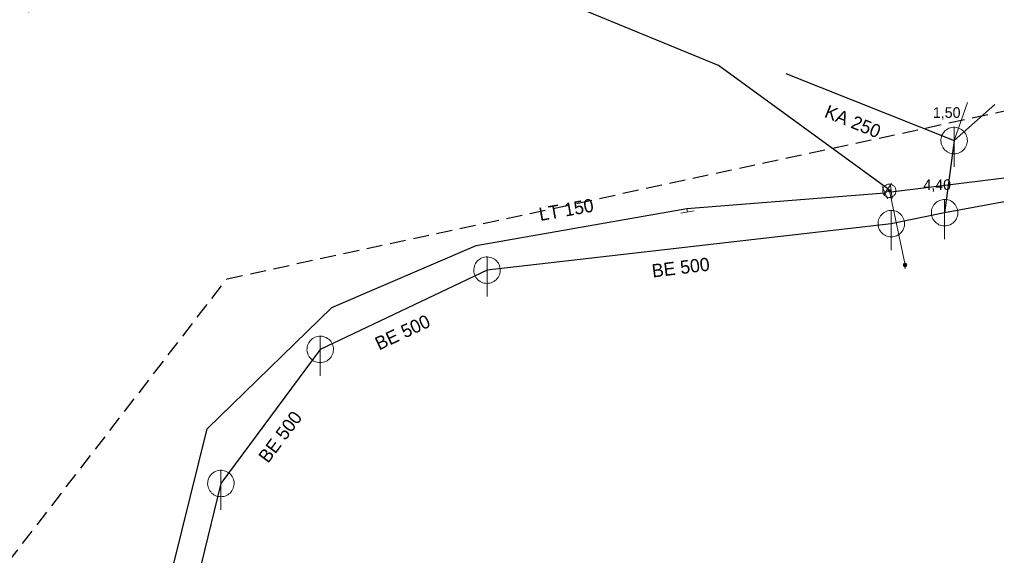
# Model space of a CAD drawing. Extents: x -687013 to -686506, y -973869 to -973672.
# Drawn here: x -686949.6 to -686875.8, y -973756 to -973715.5 of the extents above; entities that cross this region are included whole.
import ezdxf

# ---------------------------------------------------------------- set-up
doc = ezdxf.new("R2010")
doc.units = 0
doc.header["$LTSCALE"] = 0.4
doc.linetypes.add('MEDIUM_DASHED', pattern=[4.5, 3, -1.5])
doc.layers.add('1', color=7, linetype='Continuous')
for name, color, linetype, lineweight in [('11', 7, 'Continuous', 13), ('14', 7, 'Continuous', 25), ('17', 7, 'Continuous', 25), ('22', 7, 'Continuous', 13), ('34', 7, 'Continuous', 13), ('47', 7, 'Continuous', 13), ('63', 7, 'MEDIUM_DASHED', 25), ('9', 7, 'Continuous', 13)]:
    doc.layers.add(name, color=color, linetype=linetype, lineweight=lineweight)

msp = doc.modelspace()

# ---------------------------------------------------------------- linework, layer by layer
at = {"layer": '11'}
for p in [(-686877.96, -973721.82), (-686875.89, -973721.97)]:
    msp.add_line(p, (-686878.96, -973724.68), dxfattribs=at)
at = {"layer": '14'}
for p, q in [((-686891.67, -973719.62), (-686878.96, -973724.68)), ((-686849.73, -973724.67), (-686879.68, -973730.129)), ((-686883.71, -973730.96), (-686914.257, -973734.469)), ((-686914.257, -973734.469), (-686926.861, -973740.452)), ((-686926.861, -973740.452), (-686934.37, -973750.579)), ((-686934.37, -973750.579), (-686937.96, -973765.178))]:
    msp.add_line(p, q, dxfattribs=at)
at = {"layer": '14', "lineweight": 13}
for p, q in [((-686883.855, -973728.474), (-686883.979, -973728.339)), ((-686883.855, -973728.474), (-686882.671, -973734.074)), ((-686899.151, -973729.811), (-686899.109, -973730.079))]:
    msp.add_line(p, q, dxfattribs=at)
at = {"layer": '14'}
msp.add_lwpolyline([(-686878.96, -973724.68), (-686879.68, -973730.129), (-686883.71, -973730.96)], dxfattribs=at)
at = {"layer": '14', "lineweight": 13}
msp.add_lwpolyline([(-686883.709, -973728.57), (-686883.855, -973728.474), (-686884.189, -973728.62)], dxfattribs=at)
at = {"layer": '17'}
for points in [[(-686883.979, -973728.339), (-686896.774, -973719.019), (-686918.904, -973709.9), (-686935.168, -973708.778), (-686948.922, -973714.994)], [(-686778.16, -973716.008), (-686787.234, -973721.504), (-686796.6, -973724.188), (-686817.64, -973721.881), (-686819.859, -973721.829), (-686837.05, -973722.085), (-686859.074, -973725.682), (-686861.337, -973725.804), (-686883.709, -973728.57)], [(-686976.761, -973790.276), (-686962.561, -973784.848), (-686950.728, -973778.526), (-686943.195, -973771.934), (-686939.23, -973761.912), (-686935.397, -973746.442), (-686925.984, -973737.294), (-686915.07, -973732.61), (-686899.151, -973729.811), (-686884.189, -973728.62)]]:
    msp.add_lwpolyline(points, dxfattribs=at)
at = {"layer": '22'}
for p, q in [((-686878.96, -973726.68), (-686878.959, -973723.68)), ((-686879.68, -973732.13), (-686879.679, -973729.13)), ((-686883.71, -973732.96), (-686883.709, -973729.96)), ((-686914.257, -973736.469), (-686914.256, -973733.469)), ((-686926.861, -973742.452), (-686926.86, -973739.452)), ((-686934.37, -973752.579), (-686934.369, -973749.579))]:
    msp.add_line(p, q, dxfattribs=at)
for points in [[(-686877.96, -973724.68), (-686877.965, -973724.571), (-686877.983, -973724.463), (-686878.013, -973724.357), (-686878.053, -973724.256), (-686878.105, -973724.159), (-686878.167, -973724.069), (-686878.239, -973723.986), (-686878.319, -973723.912), (-686878.407, -973723.846), (-686878.501, -973723.791), (-686878.601, -973723.746), (-686878.706, -973723.713), (-686878.813, -973723.691), (-686878.922, -973723.681), (-686879.032, -973723.683), (-686879.14, -973723.697), (-686879.247, -973723.722), (-686879.35, -973723.759), (-686879.448, -973723.808), (-686879.54, -973723.866), (-686879.626, -973723.935), (-686879.703, -973724.012), (-686879.772, -973724.098), (-686879.831, -973724.19), (-686879.879, -973724.288), (-686879.916, -973724.391), (-686879.942, -973724.498), (-686879.956, -973724.606), (-686879.959, -973724.716), (-686879.949, -973724.825), (-686879.928, -973724.932), (-686879.894, -973725.036), (-686879.85, -973725.136), (-686879.795, -973725.231), (-686879.729, -973725.319), (-686879.655, -973725.399), (-686879.572, -973725.471), (-686879.482, -973725.533), (-686879.386, -973725.585), (-686879.284, -973725.626), (-686879.179, -973725.656), (-686879.071, -973725.674), (-686878.961, -973725.68), (-686878.852, -973725.674), (-686878.744, -973725.656), (-686878.639, -973725.627), (-686878.537, -973725.586), (-686878.44, -973725.534), (-686878.35, -973725.472), (-686878.267, -973725.401), (-686878.192, -973725.321), (-686878.127, -973725.233), (-686878.071, -973725.139), (-686878.027, -973725.039), (-686877.993, -973724.935), (-686877.971, -973724.827), (-686877.961, -973724.718)], [(-686878.68, -973730.13), (-686878.685, -973730.021), (-686878.703, -973729.913), (-686878.733, -973729.807), (-686878.773, -973729.706), (-686878.825, -973729.609), (-686878.887, -973729.519), (-686878.959, -973729.436), (-686879.039, -973729.362), (-686879.127, -973729.296), (-686879.221, -973729.241), (-686879.321, -973729.196), (-686879.426, -973729.163), (-686879.533, -973729.141), (-686879.642, -973729.131), (-686879.752, -973729.133), (-686879.86, -973729.147), (-686879.967, -973729.172), (-686880.07, -973729.209), (-686880.168, -973729.258), (-686880.26, -973729.316), (-686880.346, -973729.385), (-686880.423, -973729.462), (-686880.492, -973729.548), (-686880.551, -973729.64), (-686880.599, -973729.738), (-686880.636, -973729.841), (-686880.662, -973729.948), (-686880.676, -973730.056), (-686880.679, -973730.166), (-686880.669, -973730.275), (-686880.648, -973730.382), (-686880.614, -973730.486), (-686880.57, -973730.586), (-686880.515, -973730.681), (-686880.449, -973730.769), (-686880.375, -973730.849), (-686880.292, -973730.921), (-686880.202, -973730.983), (-686880.106, -973731.035), (-686880.004, -973731.076), (-686879.899, -973731.106), (-686879.791, -973731.124), (-686879.681, -973731.13), (-686879.572, -973731.124), (-686879.464, -973731.106), (-686879.359, -973731.077), (-686879.257, -973731.036), (-686879.16, -973730.984), (-686879.07, -973730.922), (-686878.987, -973730.851), (-686878.912, -973730.771), (-686878.847, -973730.683), (-686878.791, -973730.589), (-686878.747, -973730.489), (-686878.713, -973730.385), (-686878.691, -973730.277), (-686878.681, -973730.168)], [(-686882.71, -973730.96), (-686882.715, -973730.851), (-686882.733, -973730.743), (-686882.763, -973730.637), (-686882.803, -973730.536), (-686882.855, -973730.439), (-686882.917, -973730.349), (-686882.989, -973730.266), (-686883.069, -973730.192), (-686883.157, -973730.126), (-686883.251, -973730.071), (-686883.351, -973730.026), (-686883.456, -973729.993), (-686883.563, -973729.971), (-686883.672, -973729.961), (-686883.782, -973729.963), (-686883.89, -973729.977), (-686883.997, -973730.002), (-686884.1, -973730.039), (-686884.198, -973730.088), (-686884.29, -973730.146), (-686884.376, -973730.215), (-686884.453, -973730.292), (-686884.522, -973730.378), (-686884.581, -973730.47), (-686884.629, -973730.568), (-686884.666, -973730.671), (-686884.692, -973730.778), (-686884.706, -973730.886), (-686884.709, -973730.996), (-686884.699, -973731.105), (-686884.678, -973731.212), (-686884.644, -973731.316), (-686884.6, -973731.416), (-686884.545, -973731.511), (-686884.479, -973731.599), (-686884.405, -973731.679), (-686884.322, -973731.751), (-686884.232, -973731.813), (-686884.136, -973731.865), (-686884.034, -973731.906), (-686883.929, -973731.936), (-686883.821, -973731.954), (-686883.711, -973731.96), (-686883.602, -973731.954), (-686883.494, -973731.936), (-686883.389, -973731.907), (-686883.287, -973731.866), (-686883.19, -973731.814), (-686883.1, -973731.752), (-686883.017, -973731.681), (-686882.942, -973731.601), (-686882.877, -973731.513), (-686882.821, -973731.419), (-686882.777, -973731.319), (-686882.743, -973731.215), (-686882.721, -973731.107), (-686882.711, -973730.998)], [(-686913.257, -973734.469), (-686913.262, -973734.36), (-686913.28, -973734.252), (-686913.31, -973734.146), (-686913.35, -973734.045), (-686913.402, -973733.948), (-686913.464, -973733.858), (-686913.536, -973733.775), (-686913.616, -973733.701), (-686913.704, -973733.635), (-686913.798, -973733.58), (-686913.898, -973733.535), (-686914.003, -973733.502), (-686914.11, -973733.48), (-686914.219, -973733.47), (-686914.329, -973733.472), (-686914.437, -973733.486), (-686914.544, -973733.511), (-686914.647, -973733.548), (-686914.745, -973733.597), (-686914.837, -973733.655), (-686914.923, -973733.724), (-686915, -973733.801), (-686915.069, -973733.887), (-686915.128, -973733.979), (-686915.176, -973734.077), (-686915.213, -973734.18), (-686915.239, -973734.287), (-686915.253, -973734.395), (-686915.256, -973734.505), (-686915.246, -973734.614), (-686915.225, -973734.721), (-686915.191, -973734.825), (-686915.147, -973734.925), (-686915.092, -973735.02), (-686915.026, -973735.108), (-686914.952, -973735.188), (-686914.869, -973735.26), (-686914.779, -973735.322), (-686914.683, -973735.374), (-686914.581, -973735.415), (-686914.476, -973735.445), (-686914.368, -973735.463), (-686914.258, -973735.469), (-686914.149, -973735.463), (-686914.041, -973735.445), (-686913.936, -973735.416), (-686913.834, -973735.375), (-686913.737, -973735.323), (-686913.647, -973735.261), (-686913.564, -973735.19), (-686913.489, -973735.11), (-686913.424, -973735.022), (-686913.368, -973734.928), (-686913.324, -973734.828), (-686913.29, -973734.724), (-686913.268, -973734.616), (-686913.258, -973734.507)], [(-686925.861, -973740.452), (-686925.866, -973740.343), (-686925.884, -973740.235), (-686925.914, -973740.129), (-686925.954, -973740.028), (-686926.006, -973739.931), (-686926.068, -973739.841), (-686926.14, -973739.758), (-686926.22, -973739.684), (-686926.308, -973739.618), (-686926.402, -973739.563), (-686926.502, -973739.518), (-686926.607, -973739.485), (-686926.714, -973739.463), (-686926.823, -973739.453), (-686926.933, -973739.455), (-686927.041, -973739.469), (-686927.148, -973739.494), (-686927.251, -973739.531), (-686927.349, -973739.58), (-686927.441, -973739.638), (-686927.527, -973739.707), (-686927.604, -973739.784), (-686927.673, -973739.87), (-686927.732, -973739.962), (-686927.78, -973740.06), (-686927.817, -973740.163), (-686927.843, -973740.27), (-686927.857, -973740.378), (-686927.86, -973740.488), (-686927.85, -973740.597), (-686927.829, -973740.704), (-686927.795, -973740.808), (-686927.751, -973740.908), (-686927.696, -973741.003), (-686927.63, -973741.091), (-686927.556, -973741.171), (-686927.473, -973741.243), (-686927.383, -973741.305), (-686927.287, -973741.357), (-686927.185, -973741.398), (-686927.08, -973741.428), (-686926.972, -973741.446), (-686926.862, -973741.452), (-686926.753, -973741.446), (-686926.645, -973741.428), (-686926.54, -973741.399), (-686926.438, -973741.358), (-686926.341, -973741.306), (-686926.251, -973741.244), (-686926.168, -973741.173), (-686926.093, -973741.093), (-686926.028, -973741.005), (-686925.972, -973740.911), (-686925.928, -973740.811), (-686925.894, -973740.707), (-686925.872, -973740.599), (-686925.862, -973740.49)], [(-686933.37, -973750.579), (-686933.375, -973750.47), (-686933.393, -973750.362), (-686933.423, -973750.256), (-686933.463, -973750.155), (-686933.515, -973750.058), (-686933.577, -973749.968), (-686933.649, -973749.885), (-686933.729, -973749.811), (-686933.817, -973749.745), (-686933.911, -973749.69), (-686934.011, -973749.645), (-686934.116, -973749.612), (-686934.223, -973749.59), (-686934.332, -973749.58), (-686934.442, -973749.582), (-686934.55, -973749.596), (-686934.657, -973749.621), (-686934.76, -973749.658), (-686934.858, -973749.707), (-686934.95, -973749.765), (-686935.036, -973749.834), (-686935.113, -973749.911), (-686935.182, -973749.997), (-686935.241, -973750.089), (-686935.289, -973750.187), (-686935.326, -973750.29), (-686935.352, -973750.397), (-686935.366, -973750.505), (-686935.369, -973750.615), (-686935.359, -973750.724), (-686935.338, -973750.831), (-686935.304, -973750.935), (-686935.26, -973751.035), (-686935.205, -973751.13), (-686935.139, -973751.218), (-686935.065, -973751.298), (-686934.982, -973751.37), (-686934.892, -973751.432), (-686934.796, -973751.484), (-686934.694, -973751.525), (-686934.589, -973751.555), (-686934.481, -973751.573), (-686934.371, -973751.579), (-686934.262, -973751.573), (-686934.154, -973751.555), (-686934.049, -973751.526), (-686933.947, -973751.485), (-686933.85, -973751.433), (-686933.76, -973751.371), (-686933.677, -973751.3), (-686933.602, -973751.22), (-686933.537, -973751.132), (-686933.481, -973751.038), (-686933.437, -973750.938), (-686933.403, -973750.834), (-686933.381, -973750.726), (-686933.371, -973750.617)]]:
    msp.add_lwpolyline(points, close=True, dxfattribs=at)
at = {"layer": '34'}
for p, q in [((-686884.389, -973728.162), (-686883.989, -973729.078)), ((-686883.696, -973727.926), (-686884.262, -973728.75)), ((-686883.773, -973728.074), (-686883.645, -973729.065)), ((-686898.614, -973730.002), (-686899.603, -973730.154))]:
    msp.add_line(p, q, dxfattribs=at)
at = {"layer": '47'}
for points in [[(-686883.356, -973728.474), (-686883.359, -973728.422), (-686883.367, -973728.37), (-686883.381, -973728.32), (-686883.399, -973728.271), (-686883.423, -973728.224), (-686883.452, -973728.18), (-686883.485, -973728.14), (-686883.522, -973728.103), (-686883.562, -973728.07), (-686883.606, -973728.041), (-686883.653, -973728.017), (-686883.702, -973727.999), (-686883.752, -973727.985), (-686883.804, -973727.977), (-686883.856, -973727.974), (-686883.908, -973727.977), (-686883.96, -973727.985), (-686884.011, -973727.999), (-686884.059, -973728.017), (-686884.106, -973728.041), (-686884.15, -973728.07), (-686884.191, -973728.103), (-686884.228, -973728.14), (-686884.261, -973728.18), (-686884.289, -973728.224), (-686884.313, -973728.271), (-686884.332, -973728.32), (-686884.345, -973728.37), (-686884.353, -973728.422), (-686884.356, -973728.474), (-686884.353, -973728.526), (-686884.345, -973728.578), (-686884.332, -973728.629), (-686884.313, -973728.677), (-686884.289, -973728.724), (-686884.261, -973728.768), (-686884.228, -973728.809), (-686884.191, -973728.846), (-686884.15, -973728.879), (-686884.106, -973728.907), (-686884.059, -973728.931), (-686884.011, -973728.95), (-686883.96, -973728.963), (-686883.908, -973728.971), (-686883.856, -973728.974), (-686883.804, -973728.971), (-686883.752, -973728.963), (-686883.702, -973728.95), (-686883.653, -973728.931), (-686883.606, -973728.907), (-686883.562, -973728.879), (-686883.522, -973728.846), (-686883.485, -973728.809), (-686883.452, -973728.768), (-686883.423, -973728.724), (-686883.399, -973728.677), (-686883.381, -973728.629), (-686883.367, -973728.578), (-686883.359, -973728.526)], [(-686883.774, -973728.474), (-686883.774, -973728.465), (-686883.776, -973728.457), (-686883.778, -973728.449), (-686883.781, -973728.441), (-686883.785, -973728.433), (-686883.79, -973728.426), (-686883.795, -973728.419), (-686883.801, -973728.413), (-686883.808, -973728.408), (-686883.815, -973728.403), (-686883.823, -973728.399), (-686883.831, -973728.396), (-686883.839, -973728.394), (-686883.847, -973728.392), (-686883.856, -973728.392), (-686883.865, -973728.392), (-686883.873, -973728.394), (-686883.881, -973728.396), (-686883.889, -973728.399), (-686883.897, -973728.403), (-686883.904, -973728.408), (-686883.911, -973728.413), (-686883.917, -973728.419), (-686883.923, -973728.426), (-686883.927, -973728.433), (-686883.931, -973728.441), (-686883.934, -973728.449), (-686883.936, -973728.457), (-686883.938, -973728.465), (-686883.938, -973728.474), (-686883.938, -973728.483), (-686883.936, -973728.491), (-686883.934, -973728.499), (-686883.931, -973728.507), (-686883.927, -973728.515), (-686883.923, -973728.522), (-686883.917, -973728.529), (-686883.911, -973728.535), (-686883.904, -973728.541), (-686883.897, -973728.545), (-686883.889, -973728.549), (-686883.881, -973728.552), (-686883.873, -973728.554), (-686883.865, -973728.556), (-686883.856, -973728.556), (-686883.847, -973728.556), (-686883.839, -973728.554), (-686883.831, -973728.552), (-686883.823, -973728.549), (-686883.815, -973728.545), (-686883.808, -973728.541), (-686883.801, -973728.535), (-686883.795, -973728.529), (-686883.79, -973728.522), (-686883.785, -973728.515), (-686883.781, -973728.507), (-686883.778, -973728.499), (-686883.776, -973728.491), (-686883.774, -973728.483)]]:
    msp.add_lwpolyline(points, close=True, dxfattribs=at)
at = {"layer": '63'}
msp.add_lwpolyline([(-686909.784, -973869.363), (-686968.065, -973779.329), (-686968.065, -973779.329), (-686933.901, -973735.117), (-686933.901, -973735.117), (-686846.279, -973716.226), (-686846.279, -973716.226), (-686793.223, -973715.824), (-686793.223, -973715.824), (-686767.901, -973696.129), (-686767.901, -973696.129), (-686632.047, -973671.611), (-686632.047, -973671.611), (-686619.587, -973774.908), (-686619.587, -973774.908), (-686749.412, -973818.317), (-686749.412, -973818.317)], close=True, dxfattribs=at)
at = {"layer": '9'}
msp.add_line((-686882.672, -973734.201), (-686882.672, -973734.326), dxfattribs=at)
for points in [[(-686882.798, -973734.073), (-686882.797, -973734.086), (-686882.795, -973734.099), (-686882.792, -973734.112), (-686882.787, -973734.124), (-686882.781, -973734.136), (-686882.774, -973734.147), (-686882.766, -973734.157), (-686882.756, -973734.167), (-686882.746, -973734.175), (-686882.735, -973734.182), (-686882.723, -973734.188), (-686882.711, -973734.193), (-686882.698, -973734.196), (-686882.685, -973734.198), (-686882.672, -973734.201), (-686882.659, -973734.2), (-686882.646, -973734.198), (-686882.633, -973734.195), (-686882.621, -973734.19), (-686882.609, -973734.184), (-686882.598, -973734.177), (-686882.588, -973734.169), (-686882.578, -973734.159), (-686882.57, -973734.149), (-686882.563, -973734.138), (-686882.557, -973734.126), (-686882.552, -973734.114), (-686882.549, -973734.101), (-686882.547, -973734.088), (-686882.545, -973734.075), (-686882.546, -973734.062), (-686882.548, -973734.049), (-686882.551, -973734.036), (-686882.556, -973734.024), (-686882.562, -973734.012), (-686882.569, -973734.001), (-686882.577, -973733.991), (-686882.587, -973733.981), (-686882.597, -973733.973), (-686882.608, -973733.966), (-686882.62, -973733.96), (-686882.632, -973733.955), (-686882.645, -973733.952), (-686882.658, -973733.95), (-686882.671, -973733.948), (-686882.684, -973733.948), (-686882.697, -973733.95), (-686882.71, -973733.953), (-686882.722, -973733.958), (-686882.734, -973733.964), (-686882.745, -973733.971), (-686882.755, -973733.979), (-686882.765, -973733.989), (-686882.773, -973733.999), (-686882.78, -973734.01), (-686882.786, -973734.022), (-686882.791, -973734.034), (-686882.794, -973734.047), (-686882.796, -973734.06)], [(-686882.778, -973734.073), (-686882.778, -973734.084), (-686882.776, -973734.095), (-686882.773, -973734.106), (-686882.769, -973734.116), (-686882.764, -973734.126), (-686882.758, -973734.135), (-686882.751, -973734.144), (-686882.743, -973734.152), (-686882.734, -973734.159), (-686882.725, -973734.165), (-686882.715, -973734.17), (-686882.705, -973734.174), (-686882.694, -973734.177), (-686882.683, -973734.179), (-686882.672, -973734.179), (-686882.661, -973734.181), (-686882.65, -973734.179), (-686882.639, -973734.176), (-686882.629, -973734.172), (-686882.619, -973734.167), (-686882.61, -973734.161), (-686882.601, -973734.154), (-686882.593, -973734.146), (-686882.586, -973734.137), (-686882.58, -973734.128), (-686882.575, -973734.118), (-686882.571, -973734.108), (-686882.568, -973734.097), (-686882.566, -973734.086), (-686882.565, -973734.075), (-686882.565, -973734.064), (-686882.567, -973734.053), (-686882.57, -973734.042), (-686882.574, -973734.032), (-686882.579, -973734.022), (-686882.585, -973734.013), (-686882.592, -973734.004), (-686882.6, -973733.996), (-686882.609, -973733.989), (-686882.618, -973733.983), (-686882.628, -973733.978), (-686882.638, -973733.974), (-686882.649, -973733.971), (-686882.66, -973733.969), (-686882.671, -973733.968), (-686882.682, -973733.967), (-686882.693, -973733.969), (-686882.704, -973733.972), (-686882.714, -973733.976), (-686882.724, -973733.981), (-686882.733, -973733.987), (-686882.742, -973733.994), (-686882.75, -973734.002), (-686882.757, -973734.011), (-686882.763, -973734.02), (-686882.768, -973734.03), (-686882.772, -973734.04), (-686882.775, -973734.051), (-686882.777, -973734.062)], [(-686882.759, -973734.073), (-686882.758, -973734.082), (-686882.757, -973734.091), (-686882.754, -973734.1), (-686882.751, -973734.108), (-686882.747, -973734.116), (-686882.742, -973734.124), (-686882.736, -973734.131), (-686882.73, -973734.137), (-686882.723, -973734.143), (-686882.715, -973734.148), (-686882.707, -973734.152), (-686882.699, -973734.155), (-686882.69, -973734.158), (-686882.681, -973734.159), (-686882.672, -973734.162), (-686882.663, -973734.161), (-686882.654, -973734.16), (-686882.645, -973734.157), (-686882.637, -973734.154), (-686882.629, -973734.15), (-686882.621, -973734.145), (-686882.614, -973734.139), (-686882.608, -973734.133), (-686882.602, -973734.126), (-686882.597, -973734.118), (-686882.593, -973734.11), (-686882.59, -973734.102), (-686882.587, -973734.093), (-686882.586, -973734.084), (-686882.584, -973734.075), (-686882.585, -973734.066), (-686882.586, -973734.057), (-686882.589, -973734.048), (-686882.592, -973734.04), (-686882.596, -973734.032), (-686882.601, -973734.024), (-686882.607, -973734.017), (-686882.613, -973734.011), (-686882.62, -973734.005), (-686882.628, -973734), (-686882.636, -973733.996), (-686882.644, -973733.993), (-686882.653, -973733.99), (-686882.662, -973733.989), (-686882.671, -973733.987), (-686882.68, -973733.987), (-686882.689, -973733.988), (-686882.698, -973733.991), (-686882.706, -973733.994), (-686882.714, -973733.998), (-686882.722, -973734.003), (-686882.729, -973734.009), (-686882.735, -973734.015), (-686882.741, -973734.022), (-686882.746, -973734.03), (-686882.75, -973734.038), (-686882.753, -973734.046), (-686882.756, -973734.055), (-686882.757, -973734.064)], [(-686882.739, -973734.073), (-686882.739, -973734.08), (-686882.737, -973734.087), (-686882.736, -973734.094), (-686882.733, -973734.1), (-686882.73, -973734.106), (-686882.726, -973734.112), (-686882.722, -973734.118), (-686882.717, -973734.123), (-686882.711, -973734.127), (-686882.705, -973734.131), (-686882.699, -973734.134), (-686882.693, -973734.137), (-686882.686, -973734.138), (-686882.679, -973734.14), (-686882.672, -973734.141), (-686882.665, -973734.142), (-686882.658, -973734.14), (-686882.651, -973734.139), (-686882.645, -973734.136), (-686882.638, -973734.133), (-686882.633, -973734.129), (-686882.627, -973734.125), (-686882.622, -973734.12), (-686882.618, -973734.114), (-686882.614, -973734.108), (-686882.611, -973734.102), (-686882.608, -973734.096), (-686882.606, -973734.089), (-686882.605, -973734.082), (-686882.604, -973734.075), (-686882.604, -973734.068), (-686882.605, -973734.061), (-686882.607, -973734.054), (-686882.61, -973734.048), (-686882.613, -973734.041), (-686882.617, -973734.036), (-686882.621, -973734.03), (-686882.626, -973734.025), (-686882.632, -973734.021), (-686882.637, -973734.017), (-686882.644, -973734.014), (-686882.65, -973734.011), (-686882.657, -973734.009), (-686882.664, -973734.008), (-686882.671, -973734.007), (-686882.678, -973734.006), (-686882.685, -973734.007), (-686882.692, -973734.009), (-686882.698, -973734.012), (-686882.704, -973734.015), (-686882.71, -973734.019), (-686882.716, -973734.023), (-686882.721, -973734.028), (-686882.725, -973734.034), (-686882.729, -973734.039), (-686882.732, -973734.046), (-686882.735, -973734.052), (-686882.736, -973734.059), (-686882.738, -973734.066)], [(-686882.719, -973734.073), (-686882.719, -973734.078), (-686882.718, -973734.083), (-686882.717, -973734.088), (-686882.715, -973734.092), (-686882.713, -973734.097), (-686882.71, -973734.101), (-686882.707, -973734.104), (-686882.703, -973734.108), (-686882.7, -973734.111), (-686882.696, -973734.114), (-686882.691, -973734.116), (-686882.687, -973734.118), (-686882.682, -973734.119), (-686882.677, -973734.12), (-686882.672, -973734.12), (-686882.667, -973734.122), (-686882.662, -973734.121), (-686882.657, -973734.12), (-686882.653, -973734.118), (-686882.648, -973734.116), (-686882.644, -973734.113), (-686882.64, -973734.11), (-686882.637, -973734.106), (-686882.634, -973734.103), (-686882.631, -973734.099), (-686882.629, -973734.094), (-686882.627, -973734.09), (-686882.626, -973734.085), (-686882.625, -973734.08), (-686882.625, -973734.075), (-686882.624, -973734.07), (-686882.625, -973734.065), (-686882.626, -973734.06), (-686882.628, -973734.056), (-686882.63, -973734.051), (-686882.633, -973734.047), (-686882.636, -973734.043), (-686882.639, -973734.04), (-686882.643, -973734.037), (-686882.647, -973734.034), (-686882.652, -973734.032), (-686882.656, -973734.03), (-686882.661, -973734.029), (-686882.666, -973734.028), (-686882.671, -973734.027), (-686882.676, -973734.026), (-686882.681, -973734.027), (-686882.686, -973734.028), (-686882.69, -973734.03), (-686882.695, -973734.032), (-686882.699, -973734.035), (-686882.702, -973734.038), (-686882.706, -973734.041), (-686882.709, -973734.045), (-686882.712, -973734.049), (-686882.714, -973734.054), (-686882.716, -973734.058), (-686882.717, -973734.063), (-686882.718, -973734.068)], [(-686882.699, -973734.073), (-686882.699, -973734.076), (-686882.699, -973734.079), (-686882.698, -973734.081), (-686882.697, -973734.084), (-686882.696, -973734.087), (-686882.694, -973734.089), (-686882.692, -973734.091), (-686882.69, -973734.093), (-686882.688, -973734.095), (-686882.686, -973734.097), (-686882.683, -973734.098), (-686882.68, -973734.099), (-686882.678, -973734.1), (-686882.675, -973734.1), (-686882.672, -973734.1), (-686882.669, -973734.102), (-686882.666, -973734.102), (-686882.663, -973734.101), (-686882.661, -973734.1), (-686882.658, -973734.099), (-686882.656, -973734.097), (-686882.653, -973734.095), (-686882.651, -973734.093), (-686882.65, -973734.091), (-686882.648, -973734.089), (-686882.647, -973734.086), (-686882.646, -973734.083), (-686882.645, -973734.081), (-686882.645, -973734.078), (-686882.643, -973734.075), (-686882.644, -973734.072), (-686882.644, -973734.069), (-686882.645, -973734.066), (-686882.646, -973734.064), (-686882.647, -973734.061), (-686882.649, -973734.059), (-686882.65, -973734.056), (-686882.652, -973734.054), (-686882.655, -973734.053), (-686882.657, -973734.051), (-686882.66, -973734.05), (-686882.662, -973734.049), (-686882.665, -973734.048), (-686882.668, -973734.048), (-686882.671, -973734.046), (-686882.674, -973734.046), (-686882.677, -973734.046), (-686882.679, -973734.047), (-686882.682, -973734.048), (-686882.685, -973734.049), (-686882.687, -973734.051), (-686882.689, -973734.052), (-686882.691, -973734.054), (-686882.693, -973734.057), (-686882.695, -973734.059), (-686882.696, -973734.062), (-686882.697, -973734.064), (-686882.698, -973734.067), (-686882.698, -973734.07)], [(-686882.68, -973734.073), (-686882.68, -973734.074), (-686882.68, -973734.075), (-686882.679, -973734.075), (-686882.679, -973734.076), (-686882.679, -973734.077), (-686882.678, -973734.078), (-686882.678, -973734.078), (-686882.677, -973734.079), (-686882.677, -973734.079), (-686882.676, -973734.08), (-686882.675, -973734.08), (-686882.674, -973734.08), (-686882.674, -973734.081), (-686882.673, -973734.081), (-686882.672, -973734.081), (-686882.671, -973734.082), (-686882.67, -973734.082), (-686882.67, -973734.082), (-686882.669, -973734.082), (-686882.668, -973734.082), (-686882.667, -973734.081), (-686882.667, -973734.081), (-686882.666, -973734.08), (-686882.666, -973734.08), (-686882.665, -973734.079), (-686882.665, -973734.078), (-686882.664, -973734.077), (-686882.664, -973734.077), (-686882.664, -973734.076), (-686882.663, -973734.075), (-686882.663, -973734.074), (-686882.663, -973734.073), (-686882.663, -973734.073), (-686882.664, -973734.072), (-686882.664, -973734.071), (-686882.665, -973734.07), (-686882.665, -973734.07), (-686882.666, -973734.069), (-686882.666, -973734.069), (-686882.667, -973734.068), (-686882.668, -973734.068), (-686882.669, -973734.067), (-686882.669, -973734.067), (-686882.67, -973734.067), (-686882.671, -973734.066), (-686882.672, -973734.066), (-686882.673, -973734.065), (-686882.673, -973734.065), (-686882.674, -973734.066), (-686882.675, -973734.066), (-686882.676, -973734.067), (-686882.676, -973734.067), (-686882.677, -973734.068), (-686882.677, -973734.068), (-686882.678, -973734.069), (-686882.678, -973734.07), (-686882.678, -973734.071), (-686882.679, -973734.071), (-686882.679, -973734.072)]]:
    msp.add_lwpolyline(points, close=True, dxfattribs=at)
msp.add_lwpolyline([(-686882.641, -973734.292), (-686882.672, -973734.326), (-686882.703, -973734.29)], dxfattribs=at)

# ---------------------------------------------------------------- texts
at = {"layer": '1'}
for s, rotation, p in [('KA 250', 338, (-686888.836, -973722.884)), ('LT 150', 10, (-686910.236, -973730.759)), ('BE 500', 7, (-686901.737, -973735.029)), ('BE 500', 25, (-686922.417, -973740.54)), ('BE 500', 53, (-686930.806, -973749.107))]:
    msp.add_text(s, height=1, rotation=rotation, dxfattribs=at).set_placement(p)
for s, p in [('1,50', (-686880.56, -973722.968)), ('4,40', (-686881.279, -973728.418))]:
    msp.add_text(s, height=0.8, dxfattribs=at).set_placement(p)

doc.saveas('drawing.dxf')
